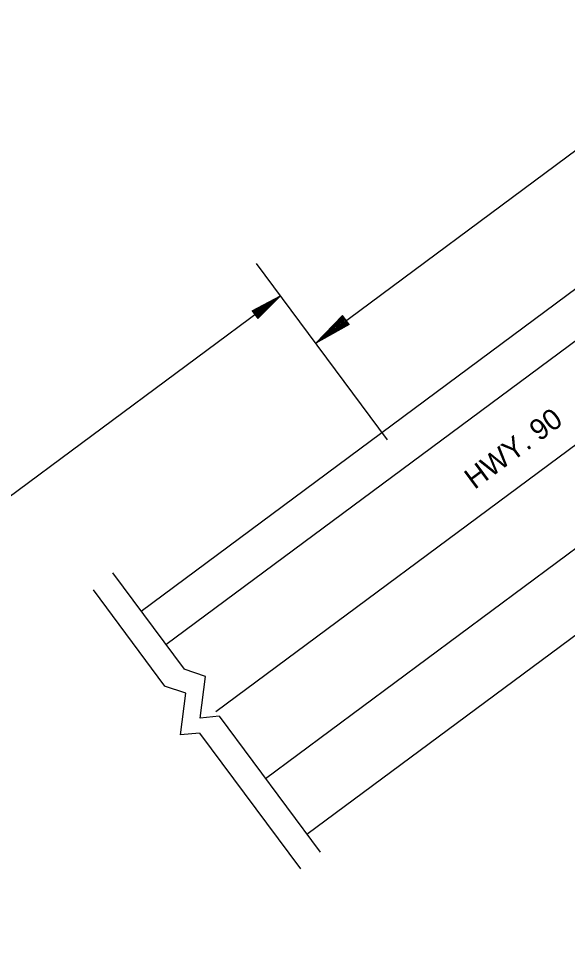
# Model space of a CAD drawing. Extents: x 998982 to 1000630, y 1875366 to 1876934.
# Drawn here: x 999794.4 to 999952, y 1875992.5 to 1876255.9 of the extents above; entities that cross this region are included whole.
import ezdxf

# ---------------------------------------------------------------- set-up
doc = ezdxf.new("R2010")
doc.units = 0
doc.layers.add('R_Border Prem', color=7, linetype='Continuous')
doc.layers.add('R_Draft', color=7, linetype='Continuous')

msp = doc.modelspace()

# ---------------------------------------------------------------- linework, layer by layer
at = {"layer": 'R_Draft'}
for p, q in [((1000139.63, 1876315.82), (999829.63, 1876085.64)), ((1000146.77, 1876306.21), (999836.77, 1876076.03)), ((1000181.11, 1876301.9), (999851.04, 1876056.81)), ((999879.74, 1876162.62), (1000060.39, 1876296.76)), ((1000175.31, 1876267.77), (999865.31, 1876037.59)), ((1000187.2, 1876251.76), (999877.2, 1876021.57)), ((999900.31, 1876134.92), (999862.76, 1876185.49)), ((999869.63, 1876176.23), (999622.25, 1875992.54)), ((999861.54, 1876171.92), (999869.63, 1876176.23)), ((999861.68, 1876171.74), (999868.42, 1876175.33)), ((999861.81, 1876171.55), (999867.16, 1876174.4)), ((999862.89, 1876170.1), (999867.16, 1876174.4)), ((999863.03, 1876169.92), (999868.42, 1876175.33)), ((999863.16, 1876169.74), (999869.63, 1876176.23)), ((999861.54, 1876171.92), (999863.16, 1876169.74)), ((999861.95, 1876171.37), (999865.95, 1876173.5)), ((999862.09, 1876171.18), (999864.72, 1876172.59)), ((999862.22, 1876171), (999863.5, 1876171.68)), ((999862.48, 1876170.66), (999863.5, 1876171.68)), ((999862.62, 1876170.47), (999864.72, 1876172.59)), ((999862.75, 1876170.29), (999865.95, 1876173.5)), ((999887.38, 1876170.54), (999879.74, 1876162.62)), ((999887.54, 1876170.32), (999881.18, 1876163.73)), ((999887.72, 1876170.1), (999882.67, 1876164.86)), ((999887.88, 1876169.89), (999884.1, 1876165.97)), ((999888.86, 1876168.6), (999884.1, 1876165.97)), ((999888.05, 1876169.67), (999885.57, 1876167.09)), ((999888.69, 1876168.82), (999885.57, 1876167.09)), ((999888.22, 1876169.45), (999887.01, 1876168.2)), ((999888.53, 1876169.04), (999887.01, 1876168.2)), ((999889.37, 1876167.95), (999887.38, 1876170.54)), ((999889.37, 1876167.95), (999879.74, 1876162.62)), ((999889.2, 1876168.16), (999881.18, 1876163.73)), ((999889.03, 1876168.38), (999882.67, 1876164.86)), ((999821.45, 1876096.66), (999841.99, 1876069)), ((999815.84, 1876091.84), (999836.38, 1876064.18)), ((999851.99, 1876055.53), (999880.96, 1876016.52)), ((999846.39, 1876050.71), (999875.35, 1876011.7))]:
    msp.add_line(p, q, dxfattribs=at)
for points in [[(999851.99, 1876055.53), (999846.53, 1876054.97), (999848.11, 1876066.97), (999841.99, 1876069)], [(999846.39, 1876050.71), (999840.93, 1876050.15), (999842.5, 1876062.15), (999836.38, 1876064.18)]]:
    msp.add_lwpolyline(points, dxfattribs=at)

# ---------------------------------------------------------------- texts
at = {"layer": 'R_Border Prem'}
msp.add_text('HWY. 90', height=6, rotation=36.5953, dxfattribs=at).set_placement((999925.3, 1876120.47))

doc.saveas('drawing.dxf')
